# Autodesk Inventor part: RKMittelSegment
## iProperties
Company: Scholle und Partner GmbH
Shininess: 64.0
Length Units: 11269
Angle Units: 11279
Time Units: 11290
Mass Units: 11283
Length Display Precision: 3
Angle Display Precision: 2
Compacted: True
Part Number: RKMittelSegment
Document SubType Name: Sheet Metal
Created: 2004-10
Material: Standard
Designer: mp
Density: 0.0
Volumn: 0.0
Area: 0.0
PropertySet Name: Model Information
Control State: 0
Master: False
Checked Out: False
Author: Michael Puschner
Comments: www.scholle.de
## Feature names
1. Extrusion1
2. ExtrusionAbwicklung1
